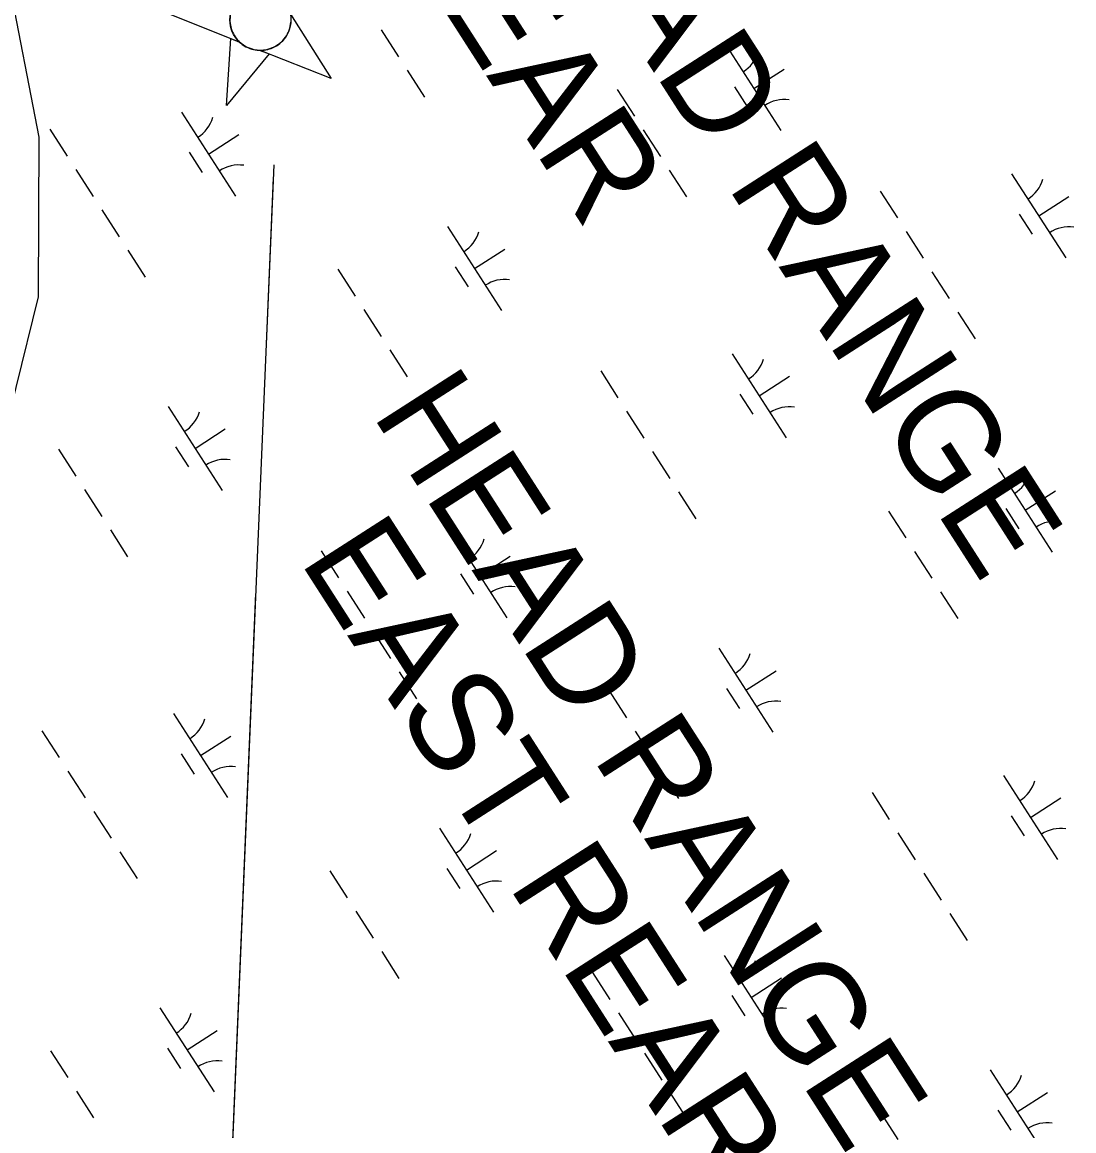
# Model space of a CAD drawing. Extents: x 3937982 to 3958556, y 219448 to 241894.
# Drawn here: x 3943640 to 3944166, y 234368 to 234922 of the extents above; entities that cross this region are included whole.
import ezdxf

# ---------------------------------------------------------------- set-up
doc = ezdxf.new("R2010")
doc.units = 0
for name, color, linetype in [('V-CHAN-NAID', 7, 'Continuous'), ('V-RIVR-RANG', 7, 'Continuous'), ('V-RRAP-FSHR', 7, 'Continuous'), ('V-TOPO-MINR', 7, 'Continuous'), ('V-WETL-SWMP', 7, 'Continuous')]:
    doc.layers.add(name, color=color, linetype=linetype)

msp = doc.modelspace()

# ---------------------------------------------------------------- linework, layer by layer
at = {"layer": 'V-CHAN-NAID'}
for points in [[(3943748.769, 234912.47), (3943713.229, 234926.604), (3943745.644, 234934.874), (3943745.336, 234930.09), (3943745.102, 234929.562), (3943744.693, 234928.478), (3943744.426, 234927.585), (3943744.19, 234926.562), (3943744.039, 234925.64), (3943743.945, 234924.716), (3943743.909, 234923.859), (3943743.927, 234922.873), (3943744.007, 234921.906), (3943744.15, 234920.933), (3943744.307, 234920.175), (3943744.524, 234919.347), (3943744.888, 234918.258), (3943745.182, 234917.536), (3943745.621, 234916.615), (3943745.993, 234915.94), (3943746.486, 234915.151), (3943746.976, 234914.462), (3943747.512, 234913.79), (3943748.157, 234913.074)], [(3943759.071, 234908.373), (3943763.525, 234906.601), (3943742.162, 234880.858), (3943744.314, 234914.242), (3943748.769, 234912.47), (3943749.419, 234911.898), (3943750.09, 234911.371), (3943751.058, 234910.71), (3943751.899, 234910.219), (3943752.872, 234909.735), (3943753.852, 234909.331), (3943754.795, 234909.015), (3943755.634, 234908.789), (3943756.605, 234908.591), (3943757.52, 234908.463), (3943758.442, 234908.39)]]:
    msp.add_lwpolyline(points, close=True, dxfattribs=at)
msp.add_lwpolyline([(3943774.166, 234926.563), (3943794.61, 234894.238), (3943759.071, 234908.373), (3943759.943, 234908.392), (3943760.985, 234908.48), (3943761.845, 234908.607), (3943762.867, 234908.825), (3943763.765, 234909.078), (3943764.562, 234909.353), (3943765.505, 234909.745), (3943766.217, 234910.092), (3943767.179, 234910.636), (3943768.038, 234911.205), (3943768.921, 234911.885), (3943769.589, 234912.472), (3943770.395, 234913.281), (3943771.122, 234914.129), (3943771.753, 234914.98), (3943772.185, 234915.643), (3943772.719, 234916.584), (3943773.156, 234917.496), (3943773.544, 234918.467), (3943773.851, 234919.413), (3943774.082, 234920.317), (3943774.285, 234921.418), (3943774.408, 234922.533)], dxfattribs=at)
msp.add_circle((3943759.178, 234923.643), 15.27, dxfattribs=at)
at = {"layer": 'V-RIVR-RANG'}
for points in [[(3943765.839, 234851.03), (3943762.058, 234761.383)], [(3943765.567, 234844.599), (3943658.865, 232314.647)], [(3943765.567, 234844.599), (3943658.865, 232314.647)], [(3943756.791, 234636.494), (3943744.571, 234346.752)]]:
    msp.add_lwpolyline(points, dxfattribs=at)
at = {"layer": 'V-RRAP-FSHR'}
msp.add_lwpolyline([(3943300.372, 233849.683), (3943331.899, 233923.208), (3943363.426, 233996.733), (3943394.887, 234070.287), (3943426.5, 234143.986), (3943457.122, 234217.688), (3943488.239, 234291.387), (3943519.301, 234365.111), (3943550.3, 234438.974), (3943580.758, 234512.837), (3943648.153, 234785.105), (3943648.444, 234864.923), (3943633.272, 234943.444)], dxfattribs=at)
at = {"layer": 'V-TOPO-MINR'}
msp.add_lwpolyline([(3943765.567, 234844.599), (3943658.865, 232314.647)], dxfattribs=at)
at = {"layer": 'V-WETL-SWMP'}
for p, q in [((3943819.658, 234918.594), (3943828.318, 234905.14)), ((3943992.673, 234910.252), (3944019.735, 234868.209)), ((3943832.648, 234898.413), (3943841.308, 234884.959)), ((3944006.204, 234889.23), (3944021.339, 234898.973)), ((3943937.806, 234888.855), (3943946.466, 234875.401)), ((3943996.469, 234890.099), (3944002.963, 234880.009)), ((3943719.676, 234877.521), (3943746.738, 234835.478)), ((3943653.811, 234868.926), (3943662.471, 234855.472)), ((3943733.207, 234856.499), (3943748.343, 234866.242)), ((3943950.796, 234868.674), (3943959.456, 234855.22)), ((3943723.472, 234857.369), (3943729.967, 234847.278)), ((3943666.801, 234848.745), (3943675.461, 234835.291)), ((3943963.786, 234848.493), (3943972.446, 234835.039)), ((3944135.238, 234846.562), (3944162.301, 234804.518)), ((3944069.373, 234837.967), (3944078.033, 234824.513)), ((3944148.77, 234825.54), (3944163.905, 234835.282)), ((3943679.791, 234828.564), (3943688.451, 234815.111)), ((3944139.034, 234826.409), (3944145.529, 234816.319)), ((3943852.805, 234820.222), (3943879.868, 234778.179)), ((3944082.363, 234817.786), (3944091.023, 234804.332)), ((3943692.781, 234808.384), (3943701.441, 234794.93)), ((3943866.336, 234799.201), (3943881.472, 234808.943)), ((3943797.939, 234798.825), (3943806.599, 234785.371)), ((3943856.601, 234800.07), (3943863.096, 234789.98)), ((3944095.353, 234797.605), (3944104.013, 234784.151)), ((3943810.929, 234778.645), (3943819.589, 234765.191)), ((3944108.343, 234777.425), (3944117.003, 234763.971)), ((3943823.919, 234758.464), (3943832.579, 234745.01)), ((3943995.371, 234756.532), (3944022.433, 234714.489)), ((3943929.506, 234747.937), (3943938.166, 234734.483)), ((3944008.902, 234735.511), (3944024.038, 234745.253)), ((3943999.167, 234736.38), (3944005.662, 234726.289)), ((3943712.938, 234730.193), (3943740, 234688.15)), ((3943942.496, 234727.756), (3943951.156, 234714.303)), ((3943726.469, 234709.171), (3943741.605, 234718.914)), ((3943716.734, 234710.04), (3943723.229, 234699.95)), ((3943658.072, 234708.796), (3943666.732, 234695.342)), ((3943955.486, 234707.576), (3943964.146, 234694.122)), ((3944128.5, 234699.234), (3944155.563, 234657.19)), ((3943671.062, 234688.615), (3943679.722, 234675.161)), ((3944142.032, 234678.212), (3944157.167, 234687.954)), ((3943968.476, 234687.395), (3943977.136, 234673.941)), ((3944073.634, 234677.837), (3944082.294, 234664.383)), ((3944132.296, 234679.081), (3944138.791, 234668.991)), ((3943684.052, 234668.434), (3943692.712, 234654.98)), ((3943855.504, 234666.503), (3943882.566, 234624.459)), ((3943789.639, 234657.908), (3943798.299, 234644.454)), ((3943869.035, 234645.481), (3943884.171, 234655.223)), ((3944086.624, 234657.656), (3944095.284, 234644.202)), ((3943859.3, 234646.35), (3943865.795, 234636.26)), ((3943802.629, 234637.727), (3943811.289, 234624.273)), ((3944099.614, 234637.475), (3944108.274, 234624.021)), ((3943815.619, 234617.546), (3943824.279, 234604.092)), ((3943988.633, 234609.204), (3944015.695, 234567.161)), ((3943828.609, 234597.365), (3943837.269, 234583.912)), ((3944002.164, 234588.182), (3944017.3, 234597.925)), ((3943933.767, 234587.807), (3943942.427, 234574.353)), ((3943992.429, 234589.052), (3943998.924, 234578.961)), ((3943715.637, 234576.473), (3943742.699, 234534.43)), ((3943649.772, 234567.878), (3943658.432, 234554.424)), ((3943946.757, 234567.626), (3943955.417, 234554.172)), ((3943729.168, 234555.452), (3943744.303, 234565.194)), ((3943719.433, 234556.321), (3943725.928, 234546.23)), ((3943662.762, 234547.697), (3943671.421, 234534.244)), ((3943959.747, 234547.446), (3943968.407, 234533.992)), ((3944131.199, 234545.514), (3944158.261, 234503.471)), ((3944065.334, 234536.919), (3944073.994, 234523.465)), ((3944144.73, 234524.492), (3944159.866, 234534.235)), ((3943675.751, 234527.517), (3943684.411, 234514.063)), ((3944134.995, 234525.361), (3944141.49, 234515.271)), ((3943848.766, 234519.175), (3943875.828, 234477.131)), ((3944078.324, 234516.738), (3944086.984, 234503.284)), ((3943688.741, 234507.336), (3943697.401, 234493.882)), ((3943862.297, 234498.153), (3943877.433, 234507.895)), ((3943852.562, 234499.022), (3943859.057, 234488.932)), ((3943793.9, 234497.777), (3943802.56, 234484.324)), ((3944091.314, 234496.557), (3944099.974, 234483.104)), ((3943806.89, 234477.597), (3943815.55, 234464.143)), ((3944104.304, 234476.377), (3944112.964, 234462.923)), ((3943819.88, 234457.416), (3943828.54, 234443.962)), ((3943991.332, 234455.484), (3944018.394, 234413.441)), ((3943925.467, 234446.889), (3943934.127, 234433.436)), ((3944004.863, 234434.463), (3944019.998, 234444.205)), ((3943995.128, 234435.332), (3944001.623, 234425.242)), ((3943708.899, 234429.145), (3943735.961, 234387.102)), ((3943938.457, 234426.709), (3943947.117, 234413.255)), ((3943722.43, 234408.123), (3943737.565, 234417.866)), ((3943654.033, 234407.748), (3943662.692, 234394.294)), ((3943712.695, 234408.993), (3943719.19, 234398.902)), ((3943951.447, 234406.528), (3943960.106, 234393.074)), ((3944124.461, 234398.186), (3944151.523, 234356.143)), ((3943667.022, 234387.567), (3943675.682, 234374.113)), ((3943964.436, 234386.347), (3943973.096, 234372.893)), ((3944137.992, 234377.164), (3944153.128, 234386.907)), ((3944069.595, 234376.789), (3944078.255, 234363.335)), ((3944128.257, 234378.033), (3944134.752, 234367.943))]:
    msp.add_line(p, q, dxfattribs=at)
for centre, start, end in [((3943991.453, 234912.585), 301.99668, 343.54034), ((3944021.353, 234866.133), 81.99668, 123.54034), ((3943718.457, 234879.854), 301.99668, 343.54034), ((3943748.357, 234833.402), 81.99668, 123.54034), ((3944134.019, 234848.894), 301.99668, 343.54034), ((3943851.586, 234822.555), 301.99668, 343.54034), ((3944163.919, 234802.443), 81.99668, 123.54034), ((3943881.486, 234776.103), 81.99668, 123.54034), ((3943994.152, 234758.865), 301.99668, 343.54034), ((3943711.719, 234732.526), 301.99668, 343.54034), ((3944024.052, 234712.413), 81.99668, 123.54034), ((3943741.619, 234686.074), 81.99668, 123.54034), ((3944127.281, 234701.566), 301.99668, 343.54034), ((3944157.181, 234655.115), 81.99668, 123.54034), ((3943854.285, 234668.835), 301.99668, 343.54034), ((3943884.185, 234622.384), 81.99668, 123.54034), ((3943987.414, 234611.537), 301.99668, 343.54034), ((3944017.314, 234565.085), 81.99668, 123.54034), ((3943714.417, 234578.806), 301.99668, 343.54034), ((3943744.317, 234532.354), 81.99668, 123.54034), ((3944129.98, 234547.847), 301.99668, 343.54034), ((3943847.547, 234521.507), 301.99668, 343.54034), ((3944159.88, 234501.395), 81.99668, 123.54034), ((3943877.447, 234475.056), 81.99668, 123.54034), ((3943990.113, 234457.817), 301.99668, 343.54034), ((3944020.013, 234411.365), 81.99668, 123.54034), ((3943707.679, 234431.478), 301.99668, 343.54034), ((3943737.579, 234385.026), 81.99668, 123.54034), ((3944123.242, 234400.519), 301.99668, 343.54034), ((3944153.142, 234354.067), 81.99668, 123.54034)]:
    msp.add_arc(centre, 17.623, start, end, dxfattribs=at)

# ---------------------------------------------------------------- texts
at = {"layer": 'V-CHAN-NAID'}
for s, p in [('HEAD RANGE', (3943881.968, 235012.687)), ('REAR', (3943821.834, 234973.979)), ('HEAD RANGE', (3943814.56, 234726.509)), ('EAST REAR', (3943778.373, 234653.187))]:
    msp.add_text(s, height=50, rotation=302.71838, dxfattribs=at).set_placement(p)

doc.saveas('drawing.dxf')
